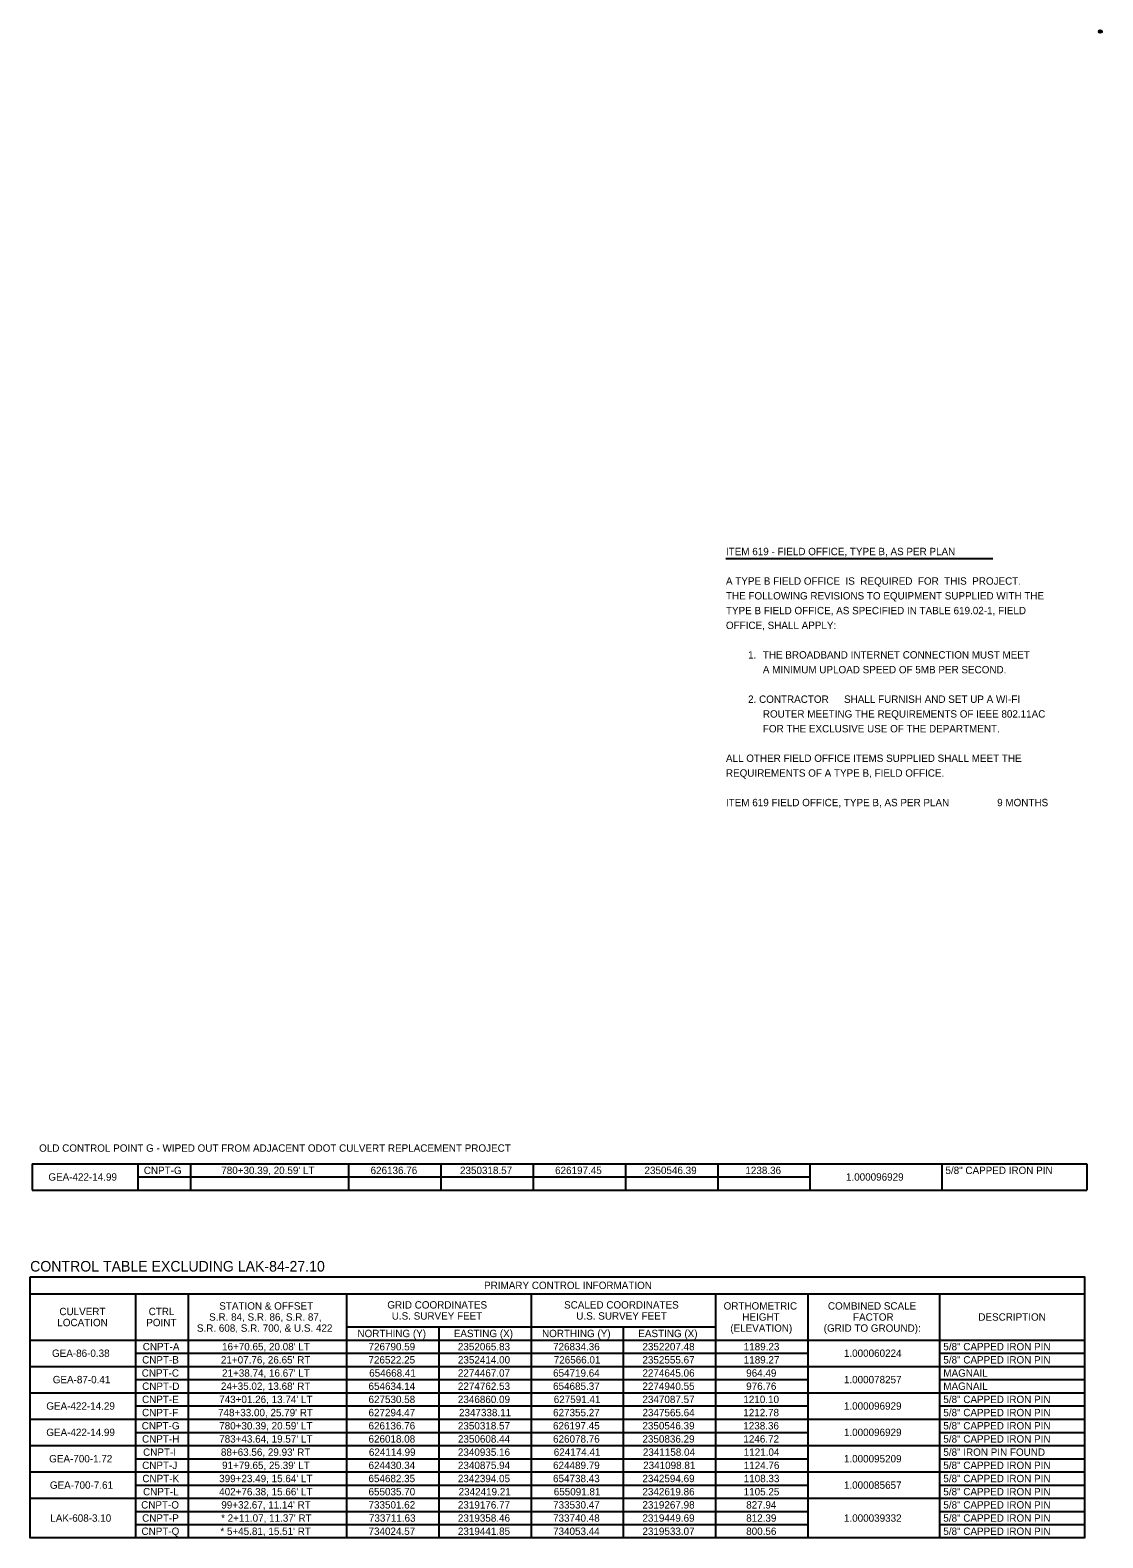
# Model space of a CAD drawing. Extents: x -23 to 159, y 0 to 91.
# Drawn here: x -22.57 to -2.23, y 1.06 to 29.65 of the extents above; entities that cross this region are included whole.
import ezdxf

# ---------------------------------------------------------------- set-up
doc = ezdxf.new("R2010")
doc.units = 0
doc.layers.add('SC_Scratch1', color=7, linetype='Continuous')

msp = doc.modelspace()

# ---------------------------------------------------------------- linework, layer by layer
at = {"layer": 'SC_Scratch1'}
for p, q in [((-2.301, 29.623), (-2.249, 29.623)), ((-2.275, 29.623), (-2.226, 29.623)), ((-9.374, 19.634), (-4.311, 19.634)), ((-22.531, 8.156), (-2.531, 8.156)), ((-22.531, 8.156), (-22.531, 7.656)), ((-20.531, 8.156), (-20.531, 7.656)), ((-19.531, 8.156), (-19.531, 7.656)), ((-16.531, 8.156), (-16.531, 7.656)), ((-14.781, 8.156), (-14.781, 7.656)), ((-13.031, 8.156), (-13.031, 7.656)), ((-11.281, 8.156), (-11.281, 7.656)), ((-9.531, 8.156), (-9.531, 7.656)), ((-7.781, 8.156), (-7.781, 7.656)), ((-5.281, 8.156), (-5.281, 7.656)), ((-2.531, 8.156), (-2.531, 7.656)), ((-20.531, 7.906), (-7.781, 7.906)), ((-22.531, 7.656), (-2.531, 7.656)), ((-22.571, 5.689), (-2.571, 5.689)), ((-20.571, 5.689), (-20.571, 1.064)), ((-19.571, 5.689), (-19.571, 1.064)), ((-16.571, 5.689), (-16.571, 1.064)), ((-13.071, 5.689), (-13.071, 1.064)), ((-9.571, 5.689), (-9.571, 1.064)), ((-7.821, 5.689), (-7.821, 1.064)), ((-5.321, 5.689), (-5.321, 1.064)), ((-16.571, 5.064), (-13.071, 5.064)), ((-14.821, 5.064), (-14.821, 1.064)), ((-13.071, 5.064), (-9.571, 5.064)), ((-11.321, 5.064), (-11.321, 1.064)), ((-22.571, 4.814), (-2.571, 4.814)), ((-20.089, 4.689), (-20.089, 4.689)), ((-18.071, 4.689), (-18.071, 4.689)), ((-15.696, 4.689), (-15.696, 4.689)), ((-13.946, 4.689), (-13.946, 4.689)), ((-12.196, 4.689), (-12.196, 4.689)), ((-10.446, 4.689), (-10.446, 4.689)), ((-8.696, 4.689), (-8.696, 4.689)), ((-5.251, 4.689), (-5.251, 4.689)), ((-22.571, 4.314), (-3.071, 4.314)), ((-22.571, 4.314), (-2.571, 4.314)), ((-21.589, 4.564), (-21.589, 4.564)), ((-20.571, 4.564), (-7.821, 4.564)), ((-20.089, 4.439), (-20.089, 4.439)), ((-18.071, 4.439), (-18.071, 4.439)), ((-15.696, 4.439), (-15.696, 4.439)), ((-13.946, 4.439), (-13.946, 4.439)), ((-12.196, 4.439), (-12.196, 4.439)), ((-10.446, 4.439), (-10.446, 4.439)), ((-8.696, 4.439), (-8.696, 4.439)), ((-6.571, 4.564), (-6.571, 4.564)), ((-5.321, 4.564), (-2.571, 4.564)), ((-5.251, 4.439), (-5.251, 4.439)), ((-21.589, 4.064), (-21.589, 4.064)), ((-20.571, 4.064), (-7.821, 4.064)), ((-20.089, 4.189), (-20.089, 4.189)), ((-18.071, 4.189), (-18.071, 4.189)), ((-15.696, 4.189), (-15.696, 4.189)), ((-13.946, 4.189), (-13.946, 4.189)), ((-12.196, 4.189), (-12.196, 4.189)), ((-10.446, 4.189), (-10.446, 4.189)), ((-8.696, 4.189), (-8.696, 4.189)), ((-6.571, 4.064), (-6.571, 4.064)), ((-5.321, 4.064), (-2.571, 4.064)), ((-5.251, 4.189), (-5.251, 4.189)), ((-22.571, 3.814), (-2.571, 3.814)), ((-20.089, 3.939), (-20.089, 3.939)), ((-18.071, 3.939), (-18.071, 3.939)), ((-15.696, 3.939), (-15.696, 3.939)), ((-13.946, 3.939), (-13.946, 3.939)), ((-12.196, 3.939), (-12.196, 3.939)), ((-10.446, 3.939), (-10.446, 3.939)), ((-8.696, 3.939), (-8.696, 3.939)), ((-5.251, 3.939), (-5.251, 3.939)), ((-21.589, 3.564), (-21.589, 3.564)), ((-20.571, 3.564), (-7.821, 3.564)), ((-20.089, 3.689), (-20.089, 3.689)), ((-20.089, 3.439), (-20.089, 3.439)), ((-18.071, 3.689), (-18.071, 3.689)), ((-18.071, 3.439), (-18.071, 3.439)), ((-15.696, 3.689), (-15.696, 3.689)), ((-15.696, 3.439), (-15.696, 3.439)), ((-13.946, 3.689), (-13.946, 3.689)), ((-13.946, 3.439), (-13.946, 3.439)), ((-12.196, 3.689), (-12.196, 3.689)), ((-12.196, 3.439), (-12.196, 3.439)), ((-10.446, 3.689), (-10.446, 3.689)), ((-10.446, 3.439), (-10.446, 3.439)), ((-8.696, 3.689), (-8.696, 3.689)), ((-8.696, 3.439), (-8.696, 3.439)), ((-6.571, 3.564), (-6.571, 3.564)), ((-5.321, 3.564), (-2.571, 3.564)), ((-5.251, 3.689), (-5.251, 3.689)), ((-5.251, 3.439), (-5.251, 3.439)), ((-22.571, 3.314), (-2.571, 3.314)), ((-20.089, 3.189), (-20.089, 3.189)), ((-18.071, 3.189), (-18.071, 3.189)), ((-15.696, 3.189), (-15.696, 3.189)), ((-13.946, 3.189), (-13.946, 3.189)), ((-12.196, 3.189), (-12.196, 3.189)), ((-10.446, 3.189), (-10.446, 3.189)), ((-8.696, 3.189), (-8.696, 3.189)), ((-5.251, 3.189), (-5.251, 3.189)), ((-21.589, 3.064), (-21.589, 3.064)), ((-20.571, 3.064), (-7.821, 3.064)), ((-20.089, 2.939), (-20.089, 2.939)), ((-18.071, 2.939), (-18.071, 2.939)), ((-15.696, 2.939), (-15.696, 2.939)), ((-13.946, 2.939), (-13.946, 2.939)), ((-12.196, 2.939), (-12.196, 2.939)), ((-10.446, 2.939), (-10.446, 2.939)), ((-8.696, 2.939), (-8.696, 2.939)), ((-6.571, 3.064), (-6.571, 3.064)), ((-5.321, 3.064), (-2.571, 3.064)), ((-5.251, 2.939), (-5.251, 2.939)), ((-22.571, 2.814), (-2.571, 2.814)), ((-20.089, 2.689), (-20.089, 2.689)), ((-18.071, 2.689), (-18.071, 2.689)), ((-15.696, 2.689), (-15.696, 2.689)), ((-13.946, 2.689), (-13.946, 2.689)), ((-12.196, 2.689), (-12.196, 2.689)), ((-10.446, 2.689), (-10.446, 2.689)), ((-8.696, 2.689), (-8.696, 2.689)), ((-5.251, 2.689), (-5.251, 2.689)), ((-22.571, 2.314), (-2.571, 2.314)), ((-21.589, 2.564), (-21.589, 2.564)), ((-20.571, 2.564), (-7.821, 2.564)), ((-20.089, 2.439), (-20.089, 2.439)), ((-18.071, 2.439), (-18.071, 2.439)), ((-15.696, 2.439), (-15.696, 2.439)), ((-13.946, 2.439), (-13.946, 2.439)), ((-12.196, 2.439), (-12.196, 2.439)), ((-10.446, 2.439), (-10.446, 2.439)), ((-8.696, 2.439), (-8.696, 2.439)), ((-6.571, 2.564), (-6.571, 2.564)), ((-5.321, 2.564), (-2.571, 2.564)), ((-5.251, 2.439), (-5.251, 2.439)), ((-21.589, 2.064), (-21.589, 2.064)), ((-20.571, 2.064), (-7.821, 2.064)), ((-20.089, 2.189), (-20.089, 2.189)), ((-18.071, 2.189), (-18.071, 2.189)), ((-15.696, 2.189), (-15.696, 2.189)), ((-13.946, 2.189), (-13.946, 2.189)), ((-12.196, 2.189), (-12.196, 2.189)), ((-10.446, 2.189), (-10.446, 2.189)), ((-8.696, 2.189), (-8.696, 2.189)), ((-6.571, 2.064), (-6.571, 2.064)), ((-5.321, 2.064), (-2.571, 2.064)), ((-5.251, 2.189), (-5.251, 2.189)), ((-22.571, 1.814), (-2.571, 1.814)), ((-20.089, 1.939), (-20.089, 1.939)), ((-18.071, 1.939), (-18.071, 1.939)), ((-15.696, 1.939), (-15.696, 1.939)), ((-13.946, 1.939), (-13.946, 1.939)), ((-12.196, 1.939), (-12.196, 1.939)), ((-10.446, 1.939), (-10.446, 1.939)), ((-8.696, 1.939), (-8.696, 1.939)), ((-5.251, 1.939), (-5.251, 1.939)), ((-21.589, 1.439), (-21.589, 1.439)), ((-20.571, 1.564), (-7.821, 1.564)), ((-20.089, 1.689), (-20.089, 1.689)), ((-20.089, 1.439), (-20.089, 1.439)), ((-18.071, 1.689), (-18.071, 1.689)), ((-18.071, 1.439), (-18.071, 1.439)), ((-15.696, 1.689), (-15.696, 1.689)), ((-15.696, 1.439), (-15.696, 1.439)), ((-13.946, 1.689), (-13.946, 1.689)), ((-13.946, 1.439), (-13.946, 1.439)), ((-12.196, 1.689), (-12.196, 1.689)), ((-12.196, 1.439), (-12.196, 1.439)), ((-10.446, 1.689), (-10.446, 1.689)), ((-10.446, 1.439), (-10.446, 1.439)), ((-8.696, 1.689), (-8.696, 1.689)), ((-8.696, 1.439), (-8.696, 1.439)), ((-6.571, 1.439), (-6.571, 1.439)), ((-5.321, 1.564), (-2.571, 1.564)), ((-5.251, 1.689), (-5.251, 1.689)), ((-5.251, 1.439), (-5.251, 1.439)), ((-20.571, 1.314), (-7.821, 1.314)), ((-20.089, 1.189), (-20.089, 1.189)), ((-18.071, 1.189), (-18.071, 1.189)), ((-15.696, 1.189), (-15.696, 1.189)), ((-13.946, 1.189), (-13.946, 1.189)), ((-12.196, 1.189), (-12.196, 1.189)), ((-10.446, 1.189), (-10.446, 1.189)), ((-8.696, 1.189), (-8.696, 1.189)), ((-5.321, 1.314), (-2.571, 1.314)), ((-5.251, 1.189), (-5.251, 1.189))]:
    msp.add_line(p, q, dxfattribs=at)
msp.add_lwpolyline([(-22.571, 6.014), (-2.571, 6.014), (-2.571, 1.064), (-22.571, 1.064)], close=True, dxfattribs=at)
msp.add_circle((-2.275, 29.623), 0.026, dxfattribs=at)

# ---------------------------------------------------------------- texts
for s, height, p in [('1', 0.00328, (-2.276, 29.63)), ('Drawing', 0.00328, (-2.243, 29.63)), ('1:20', 0.00328, (-2.243, 29.613)), ('ITEM 619 - FIELD OFFICE, TYPE B, AS PER PLAN', 0.14, (-9.374, 19.695)), ('A TYPE B FIELD OFFICE  IS  REQUIRED  FOR  THIS  PROJECT.', 0.14, (-9.374, 19.135)), ('THE FOLLOWING REVISIONS TO EQUIPMENT SUPPLIED WITH THE', 0.14, (-9.374, 18.855)), ('TYPE B FIELD OFFICE, AS SPECIFIED IN TABLE 619.02-1, FIELD', 0.14, (-9.374, 18.575)), ('OFFICE, SHALL APPLY:', 0.14, (-9.374, 18.295)), ('1.', 0.14, (-8.954, 17.735)), ('THE BROADBAND INTERNET CONNECTION MUST MEET', 0.14, (-8.674, 17.735)), ('A MINIMUM UPLOAD SPEED OF 5MB PER SECOND.', 0.14, (-8.674, 17.455)), ('2. CONTRACTOR', 0.14, (-8.954, 16.895)), ('SHALL FURNISH AND SET UP A WI-FI', 0.14, (-7.134, 16.895)), ('ROUTER MEETING THE REQUIREMENTS OF IEEE 802.11AC', 0.14, (-8.674, 16.615)), ('FOR THE EXCLUSIVE USE OF THE DEPARTMENT.', 0.14, (-8.674, 16.335)), ('ALL OTHER FIELD OFFICE ITEMS SUPPLIED SHALL MEET THE', 0.14, (-9.374, 15.775)), ('REQUIREMENTS OF A TYPE B, FIELD OFFICE.', 0.14, (-9.374, 15.495)), ('ITEM 619 FIELD OFFICE, TYPE B, AS PER PLAN', 0.14, (-9.374, 14.935)), ('  9 MONTHS', 0.14, (-4.334, 14.935)), ('OLD CONTROL POINT G - WIPED OUT FROM ADJACENT ODOT CULVERT REPLACEMENT PROJECT', 0.14, (-22.4, 8.384)), ('CONTROL TABLE EXCLUDING LAK-84-27.10', 0.2, (-22.571, 6.113))]:
    msp.add_text(s, height=height, dxfattribs=at).set_placement(p)
for s, p in [('CNPT-G', (-20.415, 7.961)), ("780+30.39, 20.59' LT", (-18.946, 7.961)), ('626136.76', (-16.114, 7.961)), ('2350318.57', (-14.418, 7.961)), ('626197.45', (-12.615, 7.961)), ('2350546.39', (-10.919, 7.961)), ('1238.36', (-9.005, 7.961)), ('5/8" CAPPED IRON PIN', (-5.211, 7.961)), ('GEA-422-14.99', (-22.225, 7.836)), ('1.000096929', (-7.098, 7.836)), ('PRIMARY CONTROL INFORMATION', (-13.961, 5.781)), ('STATION & OFFSET', (-18.983, 5.391)), ('GRID COORDINATES', (-15.797, 5.411)), ('SCALED COORDINATES', (-12.444, 5.411)), ('ORTHOMETRIC', (-9.418, 5.391)), ('COMBINED SCALE', (-7.44, 5.391)), ('LOCATION', (-22.055, 5.076)), ('CULVERT', (-22.016, 5.286)), ('POINT', (-20.368, 5.076)), ('CTRL', (-20.323, 5.286)), ('S.R. 84, S.R. 86, S.R. 87, ', (-19.176, 5.181)), ('U.S. SURVEY FEET', (-15.712, 5.201)), ('U.S. SURVEY FEET', (-12.212, 5.201)), ('HEIGHT', (-9.063, 5.181)), ('FACTOR', (-6.964, 5.181)), ('DESCRIPTION', (-4.587, 5.181)), ('S.R. 608, S.R. 700, & U.S. 422', (-19.408, 4.971)), ('NORTHING (Y)', (-16.362, 4.869)), ('EASTING (X)', (-14.536, 4.869)), ('NORTHING (Y)', (-12.862, 4.869)), ('EASTING (X)', (-11.036, 4.869)), ('(ELEVATION)', (-9.292, 4.971)), ('(GRID TO GROUND):', (-7.52, 4.971)), ('GEA-86-0.38', (-22.156, 4.494)), ('CNPT-A', (-20.435, 4.619)), ("16+70.65, 20.08' LT", (-18.931, 4.619)), ('726790.59', (-16.153, 4.619)), ('2352065.83', (-14.458, 4.619)), ('726834.36', (-12.653, 4.619)), ('2352207.48', (-10.958, 4.619)), ('1189.23', (-9.037, 4.619)), ('1.000060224', (-7.137, 4.494)), ('5/8" CAPPED IRON PIN', (-5.251, 4.619)), ('CNPT-B', (-20.446, 4.369)), ("21+07.76, 26.65' RT", (-18.952, 4.369)), ('726522.25', (-16.154, 4.369)), ('2352414.00', (-14.457, 4.369)), ('726566.01', (-12.64, 4.369)), ('2352555.67', (-10.958, 4.369)), ('1189.27', (-9.037, 4.369)), ('5/8" CAPPED IRON PIN', (-5.251, 4.369)), ('GEA-87-0.41', (-22.142, 3.994)), ('CNPT-C', (-20.454, 4.119)), ('CNPT-D', (-20.446, 3.869)), ("24+35.02, 13.68' RT", (-18.952, 3.869)), ("21+38.74, 16.67' LT", (-18.931, 4.119)), ('654634.14', (-16.153, 3.869)), ('654668.41', (-16.14, 4.119)), ('2274467.07', (-14.458, 4.119)), ('2274762.53', (-14.458, 3.869)), ('654685.37', (-12.653, 3.869)), ('654719.64', (-12.653, 4.119)), ('2274940.55', (-10.958, 3.869)), ('2274645.06', (-10.958, 4.119)), ('964.49', (-8.99, 4.119)), ('976.76', (-8.99, 3.869)), ('1.000078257', (-7.137, 3.994)), ('MAGNAIL', (-5.251, 4.119)), ('MAGNAIL', (-5.251, 3.869)), ('CNPT-E', (-20.448, 3.619)), ("743+01.26, 13.74' LT", (-18.985, 3.619)), ('627530.58', (-16.153, 3.619)), ('2346860.09', (-14.458, 3.619)), ('627591.41', (-12.64, 3.619)), ('2347087.57', (-10.958, 3.619)), ('1210.10', (-9.044, 3.619)), ('5/8" CAPPED IRON PIN', (-5.251, 3.619)), ('GEA-422-14.29', (-22.264, 3.494)), ('CNPT-F', (-20.448, 3.369)), ("748+33.00, 25.79' RT", (-19.007, 3.369)), ('627294.47', (-16.153, 3.369)), ('2347338.11', (-14.437, 3.369)), ('627355.27', (-12.653, 3.369)), ('2347565.64', (-10.957, 3.369)), ('1212.78', (-9.045, 3.369)), ('1.000096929', (-7.137, 3.494)), ('5/8" CAPPED IRON PIN', (-5.251, 3.369)), ('CNPT-G', (-20.454, 3.119)), ("780+30.39, 20.59' LT", (-18.985, 3.119)), ('626136.76', (-16.153, 3.119)), ('2350318.57', (-14.458, 3.119)), ('626197.45', (-12.654, 3.119)), ('2350546.39', (-10.958, 3.119)), ('1238.36', (-9.045, 3.119)), ('5/8" CAPPED IRON PIN', (-5.251, 3.119)), ('GEA-422-14.99', (-22.264, 2.994)), ('CNPT-H', (-20.448, 2.869)), ("783+43.64, 19.57' LT", (-18.985, 2.869)), ('626018.08', (-16.153, 2.869)), ('2350608.44', (-14.457, 2.869)), ('626078.76', (-12.653, 2.869)), ('2350836.29', (-10.958, 2.869)), ('1246.72', (-9.044, 2.869)), ('1.000096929', (-7.137, 2.994)), ('5/8" CAPPED IRON PIN', (-5.251, 2.869)), ('GEA-700-1.72', (-22.209, 2.494)), ('CNPT-I', (-20.428, 2.619)), ("88+63.56, 29.93' RT", (-18.952, 2.619)), ('624114.99', (-16.146, 2.619)), ('2340935.16', (-14.458, 2.619)), ('624174.41', (-12.64, 2.619)), ('2341158.04', (-10.95, 2.619)), ('1121.04', (-9.037, 2.619)), ('1.000095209', (-7.137, 2.494)), ('5/8" IRON PIN FOUND', (-5.251, 2.619)), ('CNPT-J', (-20.446, 2.369)), ("91+79.65, 25.39' LT", (-18.931, 2.369)), ('624430.34', (-16.153, 2.369)), ('2340875.94', (-14.457, 2.369)), ('624489.79', (-12.653, 2.369)), ('2341098.81', (-10.944, 2.369)), ('1124.76', (-9.037, 2.369)), ('5/8" CAPPED IRON PIN', (-5.251, 2.369)), ('GEA-700-7.61', (-22.196, 1.994)), ('CNPT-K', (-20.442, 2.119)), ('CNPT-L', (-20.429, 1.869)), ("402+76.38, 15.66' LT", (-18.985, 1.869)), ("399+23.49, 15.64' LT", (-18.985, 2.119)), ('654682.35', (-16.154, 2.119)), ('655035.70', (-16.153, 1.869)), ('2342394.05', (-14.458, 2.119)), ('2342419.21', (-14.444, 1.869)), ('654738.43', (-12.653, 2.119)), ('655091.81', (-12.64, 1.869)), ('2342594.69', (-10.958, 2.119)), ('2342619.86', (-10.958, 1.869)), ('1105.25', (-9.038, 1.869)), ('1108.33', (-9.037, 2.119)), ('1.000085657', (-7.137, 1.994)), ('5/8" CAPPED IRON PIN', (-5.251, 2.119)), ('5/8" CAPPED IRON PIN', (-5.251, 1.869)), ('CNPT-O', (-20.465, 1.619)), ("99+32.67, 11.14' RT", (-18.945, 1.619)), ('733501.62', (-16.153, 1.619)), ('2319176.77', (-14.458, 1.619)), ('733530.47', (-12.653, 1.619)), ('2319267.98', (-10.958, 1.619)), ('827.94', (-8.99, 1.619)), ('5/8" CAPPED IRON PIN', (-5.251, 1.619)), ('LAK-608-3.10', (-22.188, 1.369)), ('CNPT-P', (-20.447, 1.369)), ("* 2+11.07, 11.37' RT", (-18.949, 1.369)), ('733711.63', (-16.146, 1.369)), ('2319358.46', (-14.458, 1.369)), ('733740.48', (-12.653, 1.369)), ('2319449.69', (-10.958, 1.369)), ('812.39', (-8.99, 1.369)), ('1.000039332', (-7.136, 1.369)), ('5/8" CAPPED IRON PIN', (-5.251, 1.369)), ('CNPT-Q', (-20.459, 1.119)), ("* 5+45.81, 15.51' RT", (-18.963, 1.119)), ('734024.57', (-16.153, 1.119)), ('2319441.85', (-14.458, 1.119)), ('734053.44', (-12.653, 1.119)), ('2319533.07', (-10.958, 1.119)), ('800.56', (-8.99, 1.119)), ('5/8" CAPPED IRON PIN', (-5.251, 1.119))]:
    msp.add_text(s, height=0.14, rotation=360, dxfattribs=at).set_placement(p)

doc.saveas('drawing.dxf')
